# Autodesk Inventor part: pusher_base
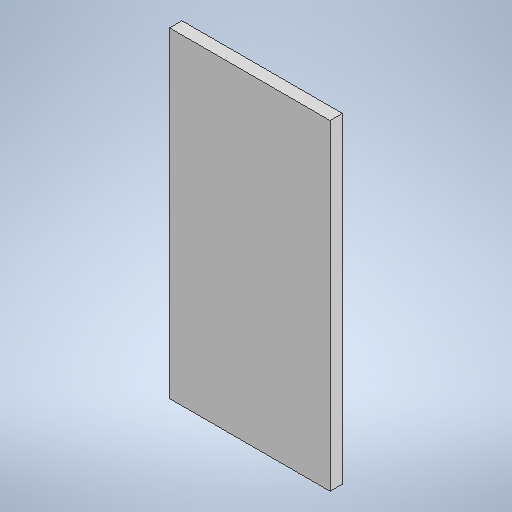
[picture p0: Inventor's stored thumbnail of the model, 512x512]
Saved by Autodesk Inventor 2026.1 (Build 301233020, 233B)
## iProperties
Created: 2026-10
Part Number: pusher_base
Material: Generic
Document SubType Name: Modeling
Designer: alolo
Density: 1 g/cm^3
Appearance: Default
Author: alolo
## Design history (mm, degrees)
sketch "Sketch1"
  geometry: L1 (0, 0)-(65, 0); L2 (65, 0)-(65, 130); L3 (65, 130)-(0, 130); L4 (0, 130)-(0, 0); L5 (0, 0)-(65, 0); L6 (65, 0)-(65, -300); L7 (65, -300)-(0, -300); L8 (0, -300)-(0, 0)
  constraints: 16 end point, 4 parallel, 2 horizontal, 2 perpendicular
  dimensions: "d0" = 65 distance of L3.end L2.end (= slide_width); "d1" = 130 distance of L2.end L1.end; "d4" = 300 distance of L5.end L6.end; "d5" = 65 distance of L6.end L7.end (= d0)
extrude "Extrusion1" new body sketch "Sketch1" distance "d2" = 5 (= wood_thickness); taper "d3" = 0 deg
body "Solid1"
other parameters: "slide_length" = 195 [user parameter], "slide_angle" = 7 deg [user parameter], "slide_width" = 65 [user parameter; used in 1 equation term], "wood_thickness" = 5 [user parameter; used in 1 equation term], "aclyric_thickness" = 6 [user parameter]
